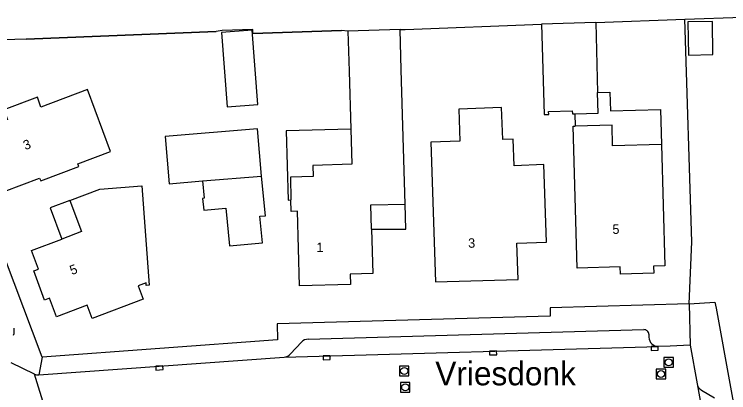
# Model space of a CAD drawing. Extents: x 140000 to 143000, y 403500 to 406000.
# Drawn here: x 140652.7 to 140728.3, y 404054.4 to 404094.4 of the extents above; entities that cross this region are included whole.
import ezdxf

# ---------------------------------------------------------------- set-up
doc = ezdxf.new("R2010")
doc.units = 0
for name, color, linetype in [('gg-afsc-erfafscheiding', 7, 'Continuous'), ('gg-afsc-hekwerk', 7, 'Continuous'), ('gg-anno-huisnummerreeks BGT', 7, 'Continuous'), ('gg-anno-openbare ruimte label', 7, 'Continuous'), ('gg-bbg-bijgebouw', 7, 'Continuous'), ('gg-bbg-gedigitaliseerde bijgebouw', 7, 'Continuous'), ('gg-bbg-hoofdgebouw', 7, 'Continuous'), ('gg-bbg-luifel en loopbrug', 7, 'Continuous'), ('gg-knt-verharding', 7, 'Continuous'), ('gt-grn-weggrens', 7, 'Continuous'), ('gt-symb-kolk', 7, 'Continuous'), ('gt-symb-rioolschacht', 7, 'Continuous')]:
    doc.layers.add(name, color=color, linetype=linetype)

# ---------------------------------------------------------------- blocks, each defined once
blk = doc.blocks.new('gt0-KOLK')
at = {"layer": 'gt-symb-kolk'}
blk.add_lwpolyline([(0, 0), (0.375, 0), (0.375, 0.4), (-0.375, 0.4), (-0.375, 0), (0, 0)], dxfattribs=at)
blk = doc.blocks.new('gt0-RS')
at = {"layer": 'gt-symb-rioolschacht'}
blk.add_lwpolyline([(-0.5, -0.5), (0.5, -0.5), (0.5, 0.5), (-0.5, 0.5)], close=True, dxfattribs=at)
blk.add_circle((0, 0), 0.375, dxfattribs=at)

msp = doc.modelspace()

# ---------------------------------------------------------------- linework, layer by layer
at = {"layer": 'gg-afsc-erfafscheiding'}
msp.add_line((140714.221, 404093.521), (140723.619, 404093.863), dxfattribs=at)
for points in [[(140723.619, 404093.863), (140729.727, 404094.082), (140750.177, 404094.888)], [(140693.506, 404092.757), (140694.048, 404092.757), (140708.473, 404093.35)], [(140724.092, 404063.792), (140724.374, 404070.339), (140723.619, 404093.863)]]:
    msp.add_lwpolyline(points, dxfattribs=at)
at = {"layer": 'gg-afsc-hekwerk'}
for p, q in [((140694.048, 404092.757), (140708.473, 404093.35)), ((140714.221, 404093.521), (140723.619, 404093.863)), ((140724.374, 404070.339), (140723.619, 404093.863)), ((140677.927, 404092.335), (140687.326, 404092.659)), ((140653.958, 404091.749), (140674.058, 404092.562))]:
    msp.add_line(p, q, dxfattribs=at)
msp.add_lwpolyline([(140723.619, 404093.863), (140729.727, 404094.082), (140750.177, 404094.888)], dxfattribs=at)
at = {"layer": 'gg-bbg-bijgebouw'}
for p, q in [((140714.221, 404093.521), (140708.473, 404093.35)), ((140714.221, 404093.521), (140714.403, 404086.125)), ((140672.599, 404076.758), (140678.86, 404077.281))]:
    msp.add_line(p, q, dxfattribs=at)
for points in [[(140708.473, 404093.35), (140708.749, 404083.778), (140709.229, 404083.792), (140709.22, 404084.112), (140711.729, 404084.184), (140711.738, 404083.864), (140711.981, 404083.871)], [(140711.981, 404083.871), (140714.457, 404083.943), (140714.403, 404086.125)], [(140678.86, 404077.281), (140678.444, 404082.258), (140668.677, 404081.45), (140669.089, 404076.468), (140672.599, 404076.758)]]:
    msp.add_lwpolyline(points, dxfattribs=at)
at = {"layer": 'gg-bbg-gedigitaliseerde bijgebouw'}
msp.add_lwpolyline([(140726.607, 404090.115), (140726.543, 404093.614), (140723.944, 404093.567), (140724.007, 404090.067), (140726.607, 404090.115)], dxfattribs=at)
at = {"layer": 'gg-bbg-hoofdgebouw'}
msp.add_line((140693.506, 404092.757), (140687.997, 404092.599), dxfattribs=at)
for points in [[(140687.997, 404092.599), (140688.115, 404088.363), (140688.286, 404082.234)], [(140694.033, 404074.326), (140693.627, 404088.52), (140693.506, 404092.757)], [(140655.528, 404084.574), (140655.143, 404085.601), (140651.612, 404084.274), (140651.997, 404083.248), (140649.191, 404082.194), (140651.644, 404075.663), (140655.389, 404077.07), (140655.505, 404076.761), (140659.549, 404078.28), (140659.433, 404078.589), (140662.896, 404079.89), (140660.443, 404086.421), (140655.528, 404084.574)], [(140705.852, 404070.179), (140709.009, 404070.29), (140708.721, 404078.485), (140705.563, 404078.374), (140705.464, 404081.182), (140704.365, 404081.144), (140704.246, 404084.511), (140699.719, 404084.352), (140699.838, 404080.984), (140696.779, 404080.877), (140697.265, 404066.084), (140705.995, 404066.352), (140705.852, 404070.179)], [(140688.286, 404082.234), (140688.39, 404078.525), (140684.292, 404078.41), (140684.325, 404077.221), (140681.906, 404077.153), (140681.972, 404074.754)], [(140721.155, 404080.604), (140721.507, 404067.808), (140720.313, 404067.774), (140720.334, 404067.004), (140716.829, 404066.907), (140716.782, 404067.678), (140712.24, 404067.545), (140711.818, 404082.548), (140712.018, 404082.553)], [(140721.155, 404080.604), (140715.987, 404080.462), (140715.926, 404082.661), (140712.018, 404082.553)], [(140658.583, 404074.701), (140661.756, 404075.895), (140666.179, 404076.232), (140666.977, 404065.746), (140666.668, 404065.722), (140666.647, 404066.001), (140665.805, 404065.686), (140666.341, 404064.253), (140660.957, 404062.236), (140660.43, 404063.641), (140657.153, 404062.413), (140656.42, 404064.37), (140655.917, 404064.181), (140654.761, 404067.266), (140655.265, 404067.454), (140654.53, 404069.416), (140657.727, 404070.621)], [(140658.583, 404074.701), (140659.813, 404071.407), (140657.727, 404070.621)], [(140690.497, 404071.681), (140690.631, 404066.996), (140688.222, 404066.927), (140688.251, 404065.836), (140682.876, 404065.686), (140682.656, 404073.563), (140682.006, 404073.545), (140681.972, 404074.754)], [(140690.497, 404071.681), (140690.424, 404074.223), (140694.033, 404074.326)]]:
    msp.add_lwpolyline(points, dxfattribs=at)
at = {"layer": 'gg-bbg-luifel en loopbrug'}
msp.add_line((140711.981, 404083.871), (140712.018, 404082.553), dxfattribs=at)
for points in [[(140678.452, 404084.848), (140677.869, 404092.692), (140674.635, 404092.451), (140675.218, 404084.608), (140678.452, 404084.848)], [(140714.403, 404086.125), (140715.7, 404086.157), (140715.755, 404084.157), (140721.053, 404084.303), (140721.155, 404080.604)], [(140688.286, 404082.234), (140681.468, 404082.043), (140681.674, 404074.746), (140681.972, 404074.754)], [(140672.599, 404076.758), (140672.803, 404074.954), (140672.618, 404074.922), (140672.748, 404073.683), (140675.073, 404073.902), (140675.466, 404069.907), (140678.949, 404070.206), (140678.676, 404073.046), (140679.285, 404073.079), (140678.86, 404077.281)], [(140658.583, 404074.701), (140656.495, 404073.921), (140657.727, 404070.621)], [(140690.497, 404071.681), (140694.111, 404071.673), (140694.033, 404074.326)]]:
    msp.add_lwpolyline(points, dxfattribs=at)
at = {"layer": 'gg-knt-verharding'}
for p, q in [((140724.092, 404063.792), (140724.178, 404059.41)), ((140683.795, 404060.04), (140719.303, 404061.047)), ((140719.817, 404060.56), (140719.825, 404060.255)), ((140681.933, 404058.491), (140683.087, 404059.731)), ((140724.178, 404059.41), (140724.917, 404055.337)), ((140681.238, 404058.153), (140720.853, 404059.283)), ((140655.307, 404056.284), (140681.238, 404058.153)), ((140654.85, 404056.348), (140652.378, 404057.536)), ((140724.917, 404055.337), (140726.723, 404045.37)), ((140725.392, 404054.658), (140726.781, 404053.838))]:
    msp.add_line(p, q, dxfattribs=at)
for points in [[(140687.997, 404092.599), (140687.326, 404092.659), (140677.927, 404092.335), (140677.944, 404092.752), (140674.689, 404092.648), (140674.058, 404092.562), (140653.958, 404091.749), (140644.316, 404091.474)], [(140655.638, 404058.157), (140647.741, 404078.995), (140644.347, 404088.032)], [(140724.092, 404063.792), (140726.814, 404063.935), (140726.926, 404063.32), (140729.978, 404046.604), (140733.029, 404029.889), (140736.065, 404013.253)], [(140724.092, 404063.792), (140709.37, 404063.364), (140709.388, 404062.472), (140680.498, 404061.656), (140680.53, 404059.985), (140655.638, 404058.157)], [(140724.178, 404059.41), (140722.078, 404059.318), (140720.853, 404059.283)], [(140654.85, 404056.348), (140655.063, 404056.287), (140655.307, 404056.284)]]:
    msp.add_lwpolyline(points, dxfattribs=at)
for centre, radius, start, end in [((140651.299, 404060.915), 1.412, 341.47887, 12.24632), ((140719.317, 404060.547), 0.5, 1.51914, 91.571), ((140720.825, 404060.283), 1.001, 181.61796, 271.58976), ((140683.797, 404059.069), 0.971, 90.12832, 137.0285), ((140681.201, 404059.113), 0.96, 272.2079, 319.66227), ((140725.894, 404055.515), 0.993, 190.31469, 239.63537)]:
    msp.add_arc(centre, radius, start, end, dxfattribs=at)
at = {"layer": 'gt-grn-weggrens'}
for p, q in [((140655.638, 404058.157), (140655.307, 404056.284)), ((140656.71, 404050.391), (140654.85, 404056.348))]:
    msp.add_line(p, q, dxfattribs=at)

# ---------------------------------------------------------------- block references
at = {"layer": 'gt-symb-kolk'}
for p, rotation in [((140703.342, 404058.784), -178.36964582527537), ((140720.431, 404059.271), -178.36964582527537), ((140685.744, 404058.282), -178.36964582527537), ((140668.036, 404057.201), -175.88103762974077)]:
    msp.add_blockref('gt0-KOLK', p, dxfattribs=dict(at, rotation=rotation))
at = {"layer": 'gt-symb-rioolschacht'}
for p in [(140721.914, 404057.592), (140693.945, 404056.683), (140721.108, 404056.36), (140694.058, 404054.954)]:
    msp.add_blockref('gt0-RS', p, dxfattribs=at)

# ---------------------------------------------------------------- texts
at = {"layer": 'gg-anno-huisnummerreeks BGT'}
for s, rotation, p in [('3', 20.5, (140653.867, 404080.013)), ('5', 1.6, (140715.978, 404071.156)), ('3', 1.7, (140700.725, 404069.692)), ('1', 1.6, (140684.671, 404069.237)), ('5', 20.5, (140658.79, 404066.805))]:
    msp.add_text(s, height=1, rotation=rotation, dxfattribs=at).set_placement(p)
at = {"layer": 'gg-anno-openbare ruimte label'}
msp.add_text('Vriesdonk', height=2.5, dxfattribs=at).set_placement((140697.235, 404055.162))

doc.saveas('drawing.dxf')
